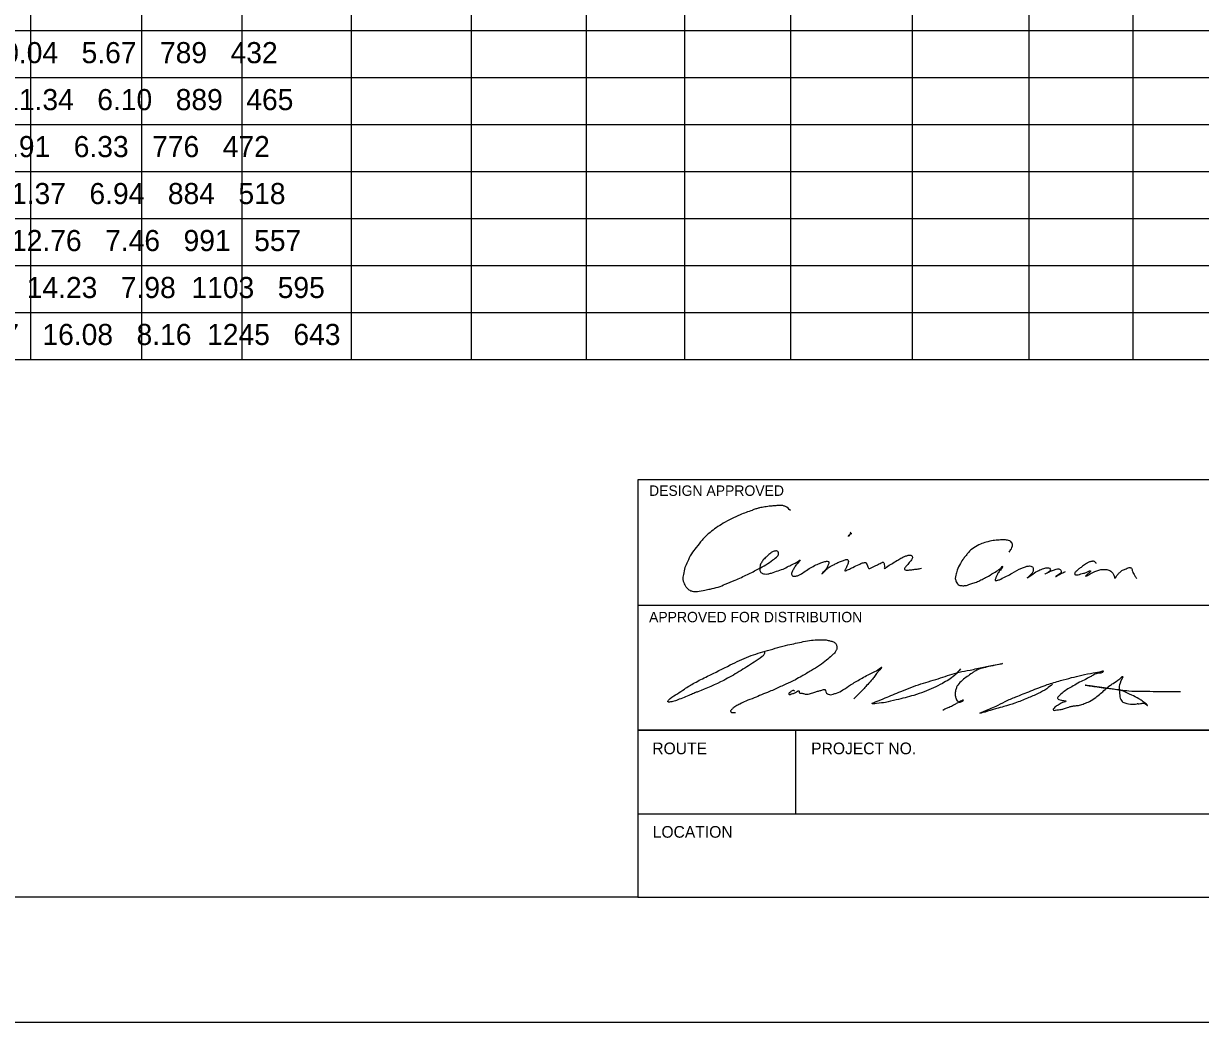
# Model space of a CAD drawing. Extents: x -0.08 to 2.83, y -0.03 to 1.92.
# Drawn here: x 1.767 to 2.355, y 0 to 0.498 of the extents above; entities that cross this region are included whole.
import ezdxf

# ---------------------------------------------------------------- set-up
doc = ezdxf.new("R2010")
doc.units = 0
for name, color, linetype in [('49', 7, 'Continuous'), ('55', 7, 'Continuous'), ('57', 7, 'Continuous'), ('63', 7, 'Continuous')]:
    doc.layers.add(name, color=color, linetype=linetype)

msp = doc.modelspace()

# ---------------------------------------------------------------- linework, layer by layer
at = {"layer": '49'}
for p, q in [((1.93079, 0.96363), (1.93079, 0.33082)), ((2.14996, 0.96363), (2.14996, 0.33082)), ((0.31609, 0.44801), (2.58572, 0.44801))]:
    msp.add_line(p, q, dxfattribs=at)
at = {"layer": '55'}
for p, q in [((1.82612, 0.9402), (1.82612, 0.33082)), ((2.04799, 0.9402), (2.04799, 0.33082)), ((2.26894, 0.9402), (2.26894, 0.33082)), ((1.77066, 0.91676), (1.77066, 0.33082)), ((1.87622, 0.91676), (1.87622, 0.33082)), ((1.99073, 0.91676), (1.99073, 0.33082)), ((2.09719, 0.91676), (2.09719, 0.33082)), ((2.2108, 0.91676), (2.2108, 0.33082)), ((2.32083, 0.91676), (2.32083, 0.33082)), ((0.34891, 0.49488), (2.58572, 0.49488)), ((0.34891, 0.47145), (2.58572, 0.47145)), ((0.34891, 0.42457), (2.58572, 0.42457)), ((0.34891, 0.40113), (2.58572, 0.40113)), ((0.34891, 0.3777), (2.58572, 0.3777)), ((0.34891, 0.35426), (2.58572, 0.35426)), ((0.31609, 0.33082), (2.58572, 0.33082)), ((0.34891, 0.33082), (2.58572, 0.33082))]:
    msp.add_line(p, q, dxfattribs=at)
for points in [[(2.15001, 0.25543), (2.14758, 0.25741), (2.14617, 0.25785), (2.14423, 0.25794), (2.14225, 0.25776), (2.1402, 0.25761), (2.13722, 0.2572), (2.13461, 0.25674), (2.13312, 0.25633), (2.13139, 0.2557), (2.1309, 0.25548), (2.1279, 0.25446), (2.12484, 0.2532), (2.1206, 0.25132), (2.11648, 0.24906), (2.11297, 0.24683), (2.10987, 0.24445), (2.10588, 0.24062), (2.10299, 0.237), (2.10059, 0.23378), (2.09857, 0.22978), (2.09735, 0.22698), (2.09658, 0.22347), (2.09632, 0.22083), (2.0965, 0.22021), (2.09681, 0.21951), (2.09723, 0.21833), (2.098, 0.21721), (2.09936, 0.21582), (2.101, 0.2152), (2.10355, 0.21505), (2.10736, 0.21566), (2.10994, 0.21625), (2.11399, 0.21726), (2.11746, 0.21865), (2.1224, 0.22067), (2.12858, 0.22356), (2.13414, 0.22632), (2.14122, 0.23075), (2.14355, 0.23265), (2.1438, 0.23291), (2.14403, 0.23351), (2.14403, 0.23426), (2.14395, 0.23467), (2.14366, 0.23506), (2.14306, 0.23523), (2.14231, 0.23519), (2.14138, 0.23496), (2.14015, 0.23417), (2.13831, 0.23262), (2.1366, 0.23096), (2.1355, 0.22937), (2.13485, 0.2278), (2.13469, 0.22641), (2.13471, 0.22546), (2.13499, 0.22483), (2.13551, 0.2243), (2.13614, 0.22393), (2.13712, 0.22378), (2.13865, 0.22378), (2.14061, 0.22424), (2.1439, 0.22538), (2.14709, 0.22656), (2.14964, 0.22791), (2.15235, 0.22918), (2.1548, 0.23064), (2.15321, 0.22863), (2.15278, 0.22814), (2.15212, 0.22718), (2.15124, 0.22569), (2.15055, 0.22402), (2.15062, 0.22327), (2.15113, 0.2227), (2.15171, 0.22264), (2.15353, 0.2229), (2.15492, 0.22351), (2.15731, 0.22511), (2.15997, 0.22683), (2.16276, 0.22826), (2.16513, 0.22931), (2.1672, 0.22997), (2.16877, 0.23003), (2.16885, 0.23001), (2.16905, 0.22994), (2.16916, 0.22971), (2.16921, 0.22923), (2.16902, 0.22873), (2.16846, 0.22743), (2.1677, 0.22608), (2.16569, 0.22382), (2.16628, 0.22431), (2.16828, 0.22641), (2.16883, 0.2268), (2.16988, 0.2275), (2.1711, 0.22812), (2.17281, 0.229), (2.17455, 0.2298), (2.17652, 0.23053), (2.17805, 0.23107), (2.17845, 0.23099), (2.17884, 0.23056), (2.17886, 0.22947), (2.17831, 0.22798), (2.17796, 0.22723), (2.17731, 0.22578), (2.17716, 0.22546), (2.17716, 0.22538), (2.17753, 0.22539), (2.17821, 0.22565), (2.17895, 0.22596), (2.18003, 0.22647), (2.18113, 0.22707), (2.18425, 0.22854), (2.18595, 0.22925), (2.18701, 0.22947), (2.18751, 0.22945), (2.18764, 0.22938), (2.18777, 0.22927), (2.18805, 0.22878), (2.18849, 0.22777), (2.18919, 0.22648), (2.1903, 0.2268), (2.19162, 0.22742), (2.19305, 0.22818), (2.19472, 0.22898), (2.1958, 0.22955), (2.19618, 0.2297), (2.19652, 0.22948), (2.19677, 0.22899), (2.19681, 0.22851), (2.19688, 0.22708), (2.19689, 0.22654), (2.19699, 0.2265), (2.19794, 0.22713), (2.20054, 0.22882), (2.20306, 0.23041), (2.20516, 0.23164), (2.20697, 0.23255), (2.20839, 0.23299), (2.21006, 0.23312), (2.2106, 0.23289), (2.21082, 0.23247), (2.2109, 0.23199), (2.21081, 0.23152), (2.2104, 0.23086), (2.20965, 0.2299), (2.20831, 0.22816), (2.20712, 0.22678), (2.20699, 0.22618), (2.20715, 0.22586), (2.2085, 0.22567), (2.20942, 0.22576), (2.21055, 0.22588), (2.21161, 0.22603), (2.21247, 0.22616), (2.21418, 0.22636), (2.21539, 0.22668)], [(2.17986, 0.24471), (2.17999, 0.24419), (2.17945, 0.24328), (2.17891, 0.24254), (2.18016, 0.24389), (2.18061, 0.24401)], [(2.25913, 0.23472), (2.26029, 0.23637), (2.26076, 0.23774), (2.26076, 0.23856), (2.26062, 0.23911), (2.26004, 0.23992), (2.25945, 0.24026), (2.2583, 0.24058), (2.25644, 0.2408), (2.25422, 0.2407), (2.25114, 0.2404), (2.24777, 0.23963), (2.2448, 0.23864), (2.24155, 0.23685), (2.23882, 0.23456), (2.2377, 0.23304), (2.2365, 0.23153), (2.23482, 0.22905), (2.23317, 0.22562), (2.23251, 0.22313), (2.2323, 0.22157), (2.2325, 0.22061), (2.23275, 0.2199), (2.23334, 0.21882), (2.23414, 0.21819), (2.23498, 0.21801), (2.2361, 0.21789), (2.23696, 0.21795), (2.23781, 0.21809), (2.23899, 0.21844), (2.24106, 0.21913), (2.24338, 0.21998), (2.24568, 0.22106), (2.24791, 0.22222), (2.25148, 0.22431), (2.25408, 0.22593), (2.25528, 0.22699), (2.25596, 0.22758), (2.2558, 0.22724), (2.25569, 0.22701), (2.25442, 0.2253), (2.25333, 0.22375), (2.25269, 0.22234), (2.25245, 0.22167), (2.25221, 0.22097), (2.25221, 0.22077), (2.25227, 0.22059), (2.25263, 0.22047), (2.25298, 0.22053), (2.2536, 0.22067), (2.25502, 0.22125), (2.26074, 0.22419), (2.26545, 0.22673), (2.26732, 0.22736), (2.26877, 0.22774), (2.26999, 0.22768), (2.27076, 0.22738), (2.27111, 0.22675), (2.27112, 0.22556), (2.27102, 0.22481), (2.27061, 0.22411), (2.26819, 0.22181), (2.27093, 0.22373), (2.27398, 0.22556), (2.27644, 0.22654), (2.27843, 0.22689), (2.27927, 0.22661), (2.27985, 0.2258), (2.27977, 0.22554), (2.27976, 0.22537), (2.27941, 0.22518), (2.2786, 0.22453), (2.27706, 0.22375), (2.27972, 0.22513), (2.28179, 0.22589), (2.28256, 0.22619), (2.28403, 0.22629), (2.28469, 0.22599), (2.28517, 0.22525), (2.28515, 0.22471), (2.28492, 0.22428), (2.28393, 0.22344), (2.28235, 0.22249), (2.28532, 0.22412), (2.28733, 0.22492)], [(2.30267, 0.22892), (2.30234, 0.22949), (2.3018, 0.22993), (2.30131, 0.23009), (2.3008, 0.23009), (2.30032, 0.23003), (2.29957, 0.22989), (2.29894, 0.22961), (2.29775, 0.22894), (2.29677, 0.22833), (2.29582, 0.22761), (2.29429, 0.22651), (2.29321, 0.22567), (2.29216, 0.2246), (2.29189, 0.22405), (2.2918, 0.22362), (2.29182, 0.22366), (2.29199, 0.22348), (2.29251, 0.22335), (2.2936, 0.22339), (2.29501, 0.22377), (2.29629, 0.22413), (2.29798, 0.2247), (2.29932, 0.22536), (2.29957, 0.22541), (2.29976, 0.2253), (2.29981, 0.2252), (2.29975, 0.225), (2.29959, 0.2248), (2.29831, 0.22373), (2.29744, 0.22287), (2.29735, 0.22276), (2.29743, 0.2227), (2.29781, 0.22277), (2.2988, 0.22329), (2.30057, 0.22435), (2.30188, 0.225), (2.30392, 0.22573), (2.3061, 0.22604), (2.30849, 0.22581), (2.30949, 0.22544), (2.31036, 0.22475), (2.31091, 0.22411), (2.3116, 0.22265), (2.31196, 0.22161), (2.3126, 0.22233), (2.31334, 0.22346), (2.31434, 0.22457), (2.31582, 0.22566), (2.31756, 0.2264), (2.31949, 0.22699), (2.31976, 0.22691), (2.32023, 0.22668), (2.3207, 0.22516), (2.32126, 0.22398), (2.32189, 0.22286), (2.32233, 0.22209), (2.32292, 0.22145)], [(2.13692, 0.18516), (2.13711, 0.18449), (2.13708, 0.18402), (2.13681, 0.18349), (2.13589, 0.18255), (2.13195, 0.17982), (2.12821, 0.17738), (2.12437, 0.17504), (2.11671, 0.17069), (2.10374, 0.16502), (2.10229, 0.16443), (2.09999, 0.1634), (2.09376, 0.16092), (2.09139, 0.16014), (2.09018, 0.15994), (2.08919, 0.15985), (2.08904, 0.15989), (2.08875, 0.16017), (2.08886, 0.16035), (2.08914, 0.16074), (2.09001, 0.16165), (2.09361, 0.16401), (2.0971, 0.16634), (2.1021, 0.16941), (2.10864, 0.17274), (2.11998, 0.17836), (2.1292, 0.18259), (2.13862, 0.18561), (2.14876, 0.18833), (2.15642, 0.19001), (2.16054, 0.19071), (2.1641, 0.1909), (2.16637, 0.19094), (2.1683, 0.19075), (2.17023, 0.19028), (2.1718, 0.18974), (2.17245, 0.18918), (2.17281, 0.18877), (2.17307, 0.18808), (2.17324, 0.18741), (2.17323, 0.18698), (2.17317, 0.1864), (2.17305, 0.18598), (2.17272, 0.18537), (2.17195, 0.18431), (2.17071, 0.18308), (2.16807, 0.18073), (2.16459, 0.17812), (2.16054, 0.17558), (2.15565, 0.17281), (2.15245, 0.171), (2.14775, 0.16877), (2.14512, 0.16756), (2.13957, 0.16509), (2.1355, 0.16347), (2.13193, 0.16192), (2.12769, 0.16032), (2.12482, 0.15889), (2.12278, 0.15776), (2.12183, 0.1571), (2.12131, 0.15676), (2.12086, 0.15632), (2.12046, 0.15586), (2.12012, 0.15542), (2.12011, 0.15537), (2.12011, 0.15526), (2.1202, 0.15509), (2.12036, 0.15488), (2.12062, 0.15472), (2.12115, 0.15459), (2.12156, 0.15459), (2.12236, 0.15462), (2.12266, 0.15463)], [(2.15215, 0.16533), (2.15165, 0.16558), (2.15087, 0.16542), (2.1497, 0.16466), (2.14918, 0.16411), (2.14918, 0.16383), (2.1495, 0.16362), (2.15043, 0.16388), (2.15113, 0.16407), (2.15248, 0.16463), (2.15357, 0.16535), (2.15403, 0.16543), (2.15418, 0.16544), (2.15443, 0.16515), (2.1544, 0.16455), (2.15476, 0.16431), (2.15544, 0.16432), (2.15619, 0.16415), (2.15697, 0.16398), (2.15772, 0.16378), (2.15893, 0.16383), (2.1601, 0.16421), (2.16212, 0.16481), (2.16403, 0.16537), (2.16566, 0.16582), (2.16712, 0.16606), (2.16767, 0.16496), (2.16804, 0.16429), (2.1689, 0.16384), (2.17004, 0.16347), (2.17128, 0.16384), (2.17298, 0.16426), (2.1762, 0.16591), (2.18, 0.16838), (2.18508, 0.17145), (2.19087, 0.17445), (2.1937, 0.17599), (2.19558, 0.1773), (2.19408, 0.17539), (2.19361, 0.17483), (2.193, 0.17404), (2.19158, 0.17212), (2.19036, 0.17057), (2.18805, 0.16806), (2.18628, 0.16609), (2.18362, 0.16346), (2.18164, 0.16142)], [(2.23491, 0.17651), (2.23186, 0.17315), (2.22584, 0.16918), (2.21679, 0.16499), (2.21159, 0.16321), (2.20276, 0.1609), (2.19747, 0.15972), (2.19293, 0.15912), (2.19072, 0.15909), (2.19235, 0.15989), (2.19737, 0.16193), (2.20515, 0.16517), (2.21517, 0.16888), (2.22498, 0.17188), (2.23419, 0.17479), (2.23965, 0.17583), (2.24639, 0.17729), (2.25314, 0.1786), (2.25576, 0.17906), (2.25005, 0.17775), (2.24376, 0.17607), (2.24298, 0.17572), (2.24203, 0.1753), (2.24067, 0.17435), (2.23819, 0.17259), (2.23585, 0.17076), (2.2335, 0.16821), (2.23281, 0.1669), (2.23236, 0.16519), (2.23225, 0.16307), (2.23247, 0.16233), (2.2327, 0.16154), (2.23327, 0.16046), (2.23374, 0.16008), (2.23426, 0.15985), (2.23515, 0.16001), (2.23578, 0.16029), (2.2364, 0.16088), (2.23548, 0.16053), (2.23352, 0.15952), (2.23198, 0.15863), (2.23092, 0.15801), (2.22859, 0.15697), (2.227, 0.15624), (2.22607, 0.15571)], [(2.28075, 0.16875), (2.27797, 0.16654), (2.27366, 0.16413), (2.26825, 0.16177), (2.26206, 0.15933), (2.25657, 0.15761), (2.25242, 0.15648), (2.24459, 0.1543), (2.24926, 0.15636), (2.25262, 0.1578), (2.25725, 0.16014), (2.26258, 0.16247), (2.26991, 0.16539), (2.27822, 0.16854), (2.28481, 0.17056), (2.29031, 0.17203), (2.29538, 0.17324), (2.30109, 0.17436), (2.30588, 0.17543), (2.30606, 0.17546), (2.30606, 0.17525), (2.30316, 0.17414), (2.3009, 0.17315), (2.29924, 0.17223), (2.29807, 0.17157), (2.29507, 0.17014), (2.29189, 0.16831), (2.28907, 0.16674), (2.28671, 0.16521), (2.28453, 0.16333), (2.28365, 0.16246), (2.28334, 0.16199), (2.28345, 0.1616), (2.28392, 0.16118), (2.28531, 0.16081), (2.28728, 0.16045), (2.28749, 0.16038), (2.28753, 0.16024), (2.28657, 0.15987), (2.2841, 0.15862), (2.28248, 0.15764), (2.2816, 0.15684), (2.28122, 0.15623), (2.28119, 0.15602), (2.28133, 0.15581), (2.28226, 0.15582), (2.28517, 0.15615), (2.28673, 0.1566), (2.28889, 0.15734), (2.29045, 0.15779), (2.29226, 0.15803), (2.29432, 0.15824), (2.29669, 0.15913), (2.29931, 0.16013), (2.30238, 0.16221), (2.30477, 0.16406), (2.30941, 0.16804), (2.31103, 0.1692), (2.31434, 0.17146), (2.31581, 0.17269), (2.31451, 0.16933), (2.31413, 0.1664), (2.31439, 0.16328), (2.31521, 0.16058), (2.31694, 0.1594), (2.32065, 0.15881), (2.32285, 0.15892), (2.32308, 0.15901), (2.32329, 0.15919), (2.32353, 0.15911), (2.32364, 0.159), (2.32467, 0.15907), (2.32563, 0.1593), (2.32699, 0.15903), (2.32804, 0.15819), (2.32817, 0.1581), (2.32825, 0.15812), (2.32825, 0.1582), (2.32813, 0.15837), (2.32721, 0.15911), (2.32701, 0.15927), (2.32506, 0.16076), (2.32392, 0.16151), (2.32032, 0.16332), (2.31627, 0.16522), (2.315, 0.16561), (2.31286, 0.166), (2.30979, 0.16645), (2.30602, 0.16682), (2.30209, 0.16741), (2.29903, 0.16786), (2.29731, 0.16826), (2.30287, 0.16758), (2.31104, 0.16647), (2.31894, 0.16545), (2.32442, 0.16523), (2.33099, 0.16521), (2.3432, 0.1651), (2.34473, 0.16507)]]:
    msp.add_spline(points, degree=3, dxfattribs=at)
at = {"layer": '63'}
for p, q in [((2.72918, 0.27077), (2.07387, 0.27077)), ((2.07387, 0.27077), (2.07387, 0.06244)), ((2.07387, 0.20828), (2.72918, 0.20828)), ((2.07387, 0.20647), (2.07387, 0.20647)), ((2.07387, 0.14578), (2.72918, 0.14578)), ((2.07387, 0.14397), (2.07387, 0.14397)), ((2.08908, 0.14583), (2.08931, 0.14583)), ((2.15266, 0.10411), (2.15266, 0.14578)), ((2.23742, 0.14583), (2.23742, 0.14583)), ((2.07387, 0.10411), (2.56251, 0.10411)), ((2.07387, 0.06244), (2.72918, 0.06244)), ((2.83333, 0), (0, 0))]:
    msp.add_line(p, q, dxfattribs=at)
msp.add_lwpolyline([(0.16668, 0.06244), (0.16668, 1.77077), (2.72918, 1.77077), (2.72918, 0.10411), (2.56251, 0.10411), (2.56251, 0.14578), (2.07387, 0.14578), (2.07387, 0.06244)], close=True, dxfattribs=at)

# ---------------------------------------------------------------- texts
at = {"layer": '55'}
for s, p in [('DESIGN APPROVED', (2.07944, 0.26274)), ('APPROVED FOR DISTRIBUTION', (2.07944, 0.19966))]:
    msp.add_text(s, height=0.0052084, dxfattribs=at).set_placement(p)
at = {"layer": '57'}
for s, p in [(" 9'  4.48   5.43   387   411    4.49   5.43   388    411   4.51   5.43   388   411    4.68   5.52   400   418    4.87   5.60   412   425    5.79   5.50   482   417    6.80   5.49   560   417    7.74   5.48   630   417    8.73   5.49   704   418   10.04   5.67   789   432", (0.35698, 0.47862)), ("10'  5.15   5.91   447   447    5.16   5.91   447    447   5.18   5.91   446   447    5.36   6.00   458   454    5.55   6.08   468   461    6.62   5.97   554   452    7.75   5.96   639   452    8.81   5.92   723   449   10.05   6.00   806   456   11.34   6.10   889   465", (0.35698, 0.45519)), (" 8'  5.01   6.04   414   450    5.02   6.03   415    450   5.10   6.09   420   454    5.14   6.09   421   454    5.33   6.20   435   463    6.19   6.14   499   458    7.10   6.14   570   458    7.94   6.13   635   457    8.82   6.19   698   462    9.91   6.33   776   472", (0.35698, 0.43175)), (" 9'  5.72   6.61   477   493    5.73   6.61   477    493   5.75   6.61   477   493    5.94   6.72   492   501    6.15   6.82   505   509    7.05   6.70   573   500    8.07   6.70   651   499    9.01   6.69   635   457   10.01   6.72   795   501   11.37   6.94   884   518", (0.35698, 0.40831)), ("10'  6.49   7.19   544   536    6.50   7.19   544    536   6.52   7.18   543   536    6.72   7.29   557   544    6.93   7.40   569   552    7.99   7.26   653   541    9.11   7.25   737   541   10.17   7.22   821   538   11.44   7.32   905   546   12.76   7.46   991   557", (0.35698, 0.38487)), ("11'  7.33   7.76   615   579    7.33   7.76   615    578   7.35   7.76   614   578    7.56   7.87   626   587    7.89   8.02   648   598    9.07   7.89   741   588   10.23   7.81   829   582   11.44   7.78   919   580   12.78   7.85  1016   585   14.23   7.98  1103   595", (0.35698, 0.36144)), ("12'  8.22   8.34   692   621    8.23   8.34   691    621   8.35   8.39   699   625    8.49   8.43   707   628    8.72   8.54   717   636   10.02   8.40   818   626   11.49   8.37   927   624   12.77   8.34  1023   622   14.26   8.41  1124   627   16.08   8.16  1245   643", (0.35698, 0.338))]:
    msp.add_text(s, height=0.01053, dxfattribs=at).set_placement(p)
at = {"layer": '63'}
for s, height, p in [('ROUTE', 0.005833, (2.08105, 0.13383)), ('PROJECT NO.', 0.0058333, (2.16034, 0.13383)), ('LOCATION', 0.005833, (2.08128, 0.09217))]:
    msp.add_text(s, height=height, dxfattribs=at).set_placement(p)

doc.saveas('drawing.dxf')
